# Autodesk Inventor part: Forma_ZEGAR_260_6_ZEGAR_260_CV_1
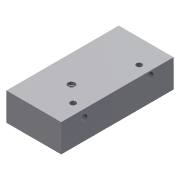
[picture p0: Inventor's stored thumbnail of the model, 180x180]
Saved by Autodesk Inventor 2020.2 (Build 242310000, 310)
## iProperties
Created: 2015-01
Part Number: Forma_ZEGAR_260_6_ZEGAR_260_CV_1
Material: Ogólny
Document SubType Name: Modeling
Designer: F.Stasiak
Density: 1 g/cm^3
Appearance: Domyślna
Catalog Web Link: www.expertbooks.pl
Manager: www.cadconsulting.pl
Company: Fabian Stasiak CAD Consulting
Author: F.Stasiak
Subject: Zbiór ćwiczeń. Autodesk Inventor 2020. Kurs Professional
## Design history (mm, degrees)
node "Forma_ZEGAR_260_4_ZEGAR_260_CV_Base"
feature "Rzeźbienie4"
feature "Gwint1" dims "d6" = 0, "d7" = 0
feature "Rzeźbienie7"
feature "Gwint4" dims "d12" = 0, "d13" = 0
feature "Rzeźbienie9"
feature "Rzeźbienie12"
feature "Bryła1::Forma_ZEGAR_260_4_ZEGAR_260_CV_Base"
tag "Bryła wyprowadzona1"
node "Bryła1"
feature "Forma_ZEGAR_260_4_ZEGAR_260_CV_Base_Bodies"
feature "Powierzchnia4"
body "Srf4"
feature "Powierzchnia7"
body "Srf7"
feature "Powierzchnia9"
body "Srf9"
feature "Powierzchnia12"
body "Srf12"
other parameters: "d0" = 0, "d1" = -26.4075, "d3" = 0, "d4" = -180 deg, "d5" = 0, "d16" = 0, "d17" = -26.4075, "d19" = 0, "d20" = -180 deg, "d21" = 0
